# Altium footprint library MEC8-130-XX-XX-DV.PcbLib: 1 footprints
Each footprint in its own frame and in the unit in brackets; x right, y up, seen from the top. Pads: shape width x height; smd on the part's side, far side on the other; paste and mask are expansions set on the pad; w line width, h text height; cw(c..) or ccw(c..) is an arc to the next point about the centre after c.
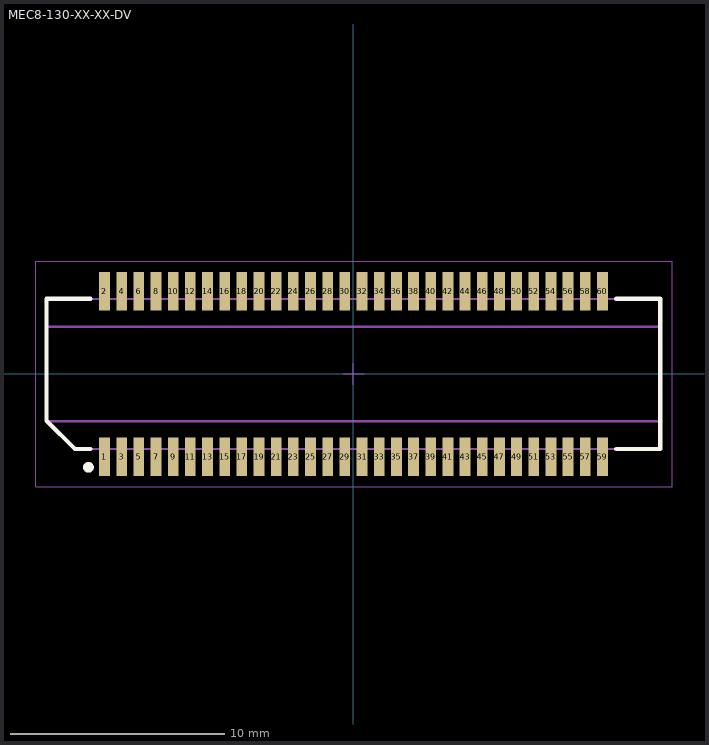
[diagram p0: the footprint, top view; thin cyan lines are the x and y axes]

## MEC8-130-XX-XX-DV [mm] "0.80mm pitch, 60 pin, mini edge-card assembly; vertical, double row"
height 8.65
pads (60):
  rect 0.5x1.8 smd mask+0: 1(-11.6,-3.85) 2(-11.6,3.85) 3(-10.8,-3.85) 4(-10.8,3.85) 5(-10,-3.85) 6(-10,3.85) 7(-9.2,-3.85) 8(-9.2,3.85) 9(-8.4,-3.85) 10(-8.4,3.85) 11(-7.6,-3.85) 12(-7.6,3.85) 13(-6.8,-3.85) 14(-6.8,3.85) 15(-6,-3.85) 16(-6,3.85) 17(-5.2,-3.85) 18(-5.2,3.85) 19(-4.4,-3.85) 20(-4.4,3.85) 21(-3.6,-3.85) 22(-3.6,3.85) 23(-2.8,-3.85) 24(-2.8,3.85) 25(-2,-3.85) 26(-2,3.85) 27(-1.2,-3.85) 28(-1.2,3.85) 29(-0.4,-3.85) 30(-0.4,3.85) 31(0.4,-3.85) 32(0.4,3.85) 33(1.2,-3.85) 34(1.2,3.85) 35(2,-3.85) 36(2,3.85) 37(2.8,-3.85) 38(2.8,3.85) 39(3.6,-3.85) 40(3.6,3.85) 41(4.4,-3.85) 42(4.4,3.85) 43(5.2,-3.85) 44(5.2,3.85) 45(6,-3.85) 46(6,3.85) 47(6.8,-3.85) 48(6.8,3.85) 49(7.6,-3.85) 50(7.6,3.85) 51(8.4,-3.85) 52(8.4,3.85) 53(9.2,-3.85) 54(9.2,3.85) 55(10,-3.85) 56(10,3.85) 57(10.8,-3.85) 58(10.8,3.85) 59(11.6,-3.85) 60(11.6,3.85)
Top Overlay:
  circle w0.25: c-12.35,-4.35 r0.125
  lines w0.2: -12.25,-3.5 -12.975,-3.5 -14.3,-2.175 -14.3,3.5 -12.25,3.5 ; 12.25,-3.5 14.3,-3.5 14.3,3.5 12.25,3.5
Mechanical 12:
  lines w0.001: -14.3,-2.2 -14.3,3.5 14.3,3.5 14.3,-3.5 -13,-3.5 -14.3,-2.2
Mechanical 13:
  lines w0.1: -14.3,2.2 14.3,2.2 ; 14.3,-2.2 -14.3,-2.2 ; -14.3,-2.2 -14.3,3.5 14.3,3.5 14.3,-3.5 -13,-3.5 -14.3,-2.2
  text ".Designator" at 0.254,0.254 h1.52
Mechanical 15:
  lines w0.05: -0.5,0 0.5,0 ; 0,-0.5 0,0.5 ; -14.8,-5.248 -14.8,5.25 14.85,5.25 14.85,-5.252 -14.798,-5.25 -14.8,-5.248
